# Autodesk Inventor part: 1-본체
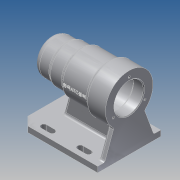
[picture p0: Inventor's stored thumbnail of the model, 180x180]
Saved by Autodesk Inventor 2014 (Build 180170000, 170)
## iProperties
Created: 2017-09
Part Number: 1-본체
Material: 알루미늄 6061
Document SubType Name: Modeling
Designer: kb542-15
Density: 2.71 g/cm^3
Appearance: 알루미늄 - 평지
Mass: 696.893 g
Surface Area: 708.801 cm^2
Volume: 257.156 cm^3
Author: kb542-15
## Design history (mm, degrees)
sketch "스케치1"
  geometry: L1 (-56, 0)-(56, 0); L2 (-56, 0)-(-56, 25); L3 (-56, 25)-(-31, 25); L4 (-31, 25)-(-31, 27); L5 (-31, 27)-(-11, 27); L6 (-11, 27)-(-11, 30); L7 (-11, 30)-(28, 30); L8 (28, 30)-(28, 34); L9 (28, 34)-(56, 34); L10 (56, 34)-(56, 21); L11 (56, 21)-(41, 21); L12 (41, 21)-(41, 24); L13 (41, 24)-(-13, 24); L14 (-13, 24)-(-13, 21); L15 (-13, 21)-(-25, 21); L16 (-25, 21)-(-25, 17.5); L17 (-25, 17.5)-(-43, 17.5); L18 (-43, 17.5)-(-43, 16); L19 (-43, 16)-(-47, 16); L20 (-47, 16)-(-47, 10.5); L21 (-47, 10.5)-(-50, 10.5); L22 (-50, 10.5)-(-50, 0); 2 further points
  constraints: 44 end point, 13 parallel, 7 perpendicular, 1 coincident, 1 collinear, 1 horizontal, 1 midpoint, 1 point on line, 1 vertical alignment
  dimensions: "d0" = 112 distance of L1.start L1.end; "d1" = 25 distance of L2.end L3.end; "d2" = 45 distance from line of L2 L6.end; "d3" = 84 distance from line of L8.end L2; "d4" = 21 diameter of L21 L1; "d5" = 32 diameter of L19 L1; "d6" = 35 diameter of L17 L1; "d7" = 42 diameter of L15 L1; "d8" = 48 diameter of L13 L1; "d9" = 42 diameter of L11 L1; "d10" = 50 diameter of L3 L1; "d11" = 54 diameter of L5 L1; "d12" = 60 diameter of L7 L1; "d13" = 68 diameter of L9 L1; "d14" = 15 distance of L10.end L11.end; "d15" = 54 distance of L12.end L13.end; "d16" = 12 distance of L14.end L15.end; "d17" = 18 distance of L16.end L17.end; "d18" = 4 distance of L18.end L19.end; "d19" = 3 distance of L20.end L21.end
revolve "회전1" sketch "스케치1" stored, may be unused: angle "d20" = 90 deg
node "작업 평면1"
sketch "스케치2"
  geometry: L1 (-56, -45)-(56, -45); L2 (56, -45)-(56, 45); L3 (56, 45)-(-56, 45); L4 (-56, 45)-(-56, -45); L5 (-56, -45)-(56, 45); L6 (56, -45)-(-56, 45); 1 further point
  constraints: 12 end point, 2 midpoint, 2 parallel, 1 horizontal, 1 perpendicular
  dimensions: "d22" = 112 distance of L2.end L3.end; "d23" = 90 distance of L1.end L2.end
extrude "돌출1" join sketch "스케치2" distance "d24" = 8; taper "d25" = 0 deg
sketch "스케치3"
  geometry: L1 (70, -45)-(70, 45) reference; L2 (70, 45)-(62, 45) reference; L3 (62, -45)-(62, 45) reference; L4 (70, -45)-(62, -45) reference; L5 (62, -35)-(26.008, -21.9); L6 (62, 35)-(26.008, 21.9); A1 r 34 centre (0, 0) between (26.008, -21.9) and (26.008, 21.9) reference
  constraints: 4 end point, 2 point on circle, 2 point on line
  dimensions: "d26" = 110 deg angle of L3 L5; "d27" = 110 deg angle of L3 L6; "d28" = 10 distance from line of L5.start L4; "d29" = 10 distance of L2.end L6.start
extrude "돌출2" join sketch "스케치3" distance "d30" = 8; taper "d31" = 0 deg
sketch "스케치4"
  geometry: L1 (56, 25)-(56, -25) reference; L2 (56, -25)-(31, -25) reference; L3 (31, -25)-(31, -27) reference; L4 (31, -27)-(11, -27) reference; L5 (11, -27)-(11, -30) reference; L6 (11, -30)-(-28, -30) reference; L7 (-28, -30)-(-28, -34) reference; L8 (-28, -34)-(-48, -34) reference; L9 (-48, -34)-(-48, -62) reference; L10 (-48, -62)-(56, -62) reference; L11 (56, -62)-(56, -70) reference; L12 (56, -70)-(-56, -70) reference; L13 (-56, -70)-(-56, -21) reference; L14 (-56, -21)-(-41, -21) reference; L15 (-41, -21)-(-41, -24) reference; L16 (-41, -24)-(13, -24) reference; L17 (13, -24)-(13, -21) reference; L18 (13, -21)-(25, -21) reference; L19 (25, -21)-(25, -17.5) reference; L20 (25, -17.5)-(43, -17.5) reference; L21 (43, -17.5)-(43, -16) reference; L22 (43, -16)-(47, -16) reference; L23 (47, -16)-(47, -10.5) reference; L24 (47, -10.5)-(50, -10.5) reference; L25 (50, -10.5)-(50, 10.5) reference; L26 (50, 10.5)-(47, 10.5) reference; L27 (47, 10.5)-(47, 16) reference; L28 (47, 16)-(43, 16) reference; L29 (43, 16)-(43, 17.5) reference; L30 (43, 17.5)-(25, 17.5) reference; L31 (25, 17.5)-(25, 21) reference; L32 (25, 21)-(13, 21) reference; L33 (13, 21)-(13, 24) reference; L34 (13, 24)-(-41, 24) reference; L35 (-41, 24)-(-41, 21) reference; L36 (-41, 21)-(-56, 21) reference; L37 (-56, 21)-(-56, 34) reference; L38 (-56, 34)-(-28, 34) reference; L39 (-28, 34)-(-28, 30) reference; L40 (-28, 30)-(11, 30) reference; L41 (11, 30)-(11, 27) reference; L42 (11, 27)-(31, 27) reference; L43 (31, 27)-(31, 25) reference; L44 (31, 25)-(56, 25) reference; L45 (34, -62)-(24.622, -27); 1 further point
  constraints: 2 end point, 2 point on line
  dimensions: "d32" = 22 distance from line of L45.start L11; "d33" = 105 deg angle of L45 L10
feature "리브1" sketch "스케치4" dims "d34" = 1, "d35" = 8, "d36" = 0, "d37" = 0, "d38" = 1, "d39" = 1
sketch "스케치5"
  geometry: L1 (48, -4)-(-34, -4) reference; L2 (56, -45)-(56, -35) reference; L3 (32, -34)-(20, -34); L4 (32, -30)-(20, -30); L5 (20, -38)-(32, -38); L6 (-20, -34)-(-32, -34); L7 (-20, -30)-(-32, -30); L8 (-32, -38)-(-20, -38); A1 r 4 centre (32, -34) between (32, -38) and (32, -30); A2 r 4 centre (20, -34) between (20, -30) and (20, -38); A3 r 4 centre (-20, -34) between (-20, -38) and (-20, -30); A4 r 4 centre (-32, -34) between (-32, -30) and (-32, -38); 3 further points
  constraints: 16 end point, 8 point on circle, 8 tangent, 4 centre point, 4 parallel, 2 midpoint, 1 horizontal alignment
  dimensions: "d40" = 24 distance from line of L2 L3.start; "d41" = 12 distance of L3.start L3.end; "d42" = 4 radius of A1; "d43" = 34 vertical distance of point (0, 0) L3.start; "d44" = 4 radius of A4; "d45" = 12 distance of L6.start L6.end; "d46" = 40 distance of L3.end L6.start
extrude "돌출3" cut sketch "스케치5" stored distance "d47" = 8; taper "d48" = 0 deg
chamfer "모따기1" distance "d49" = 12; stored, may be unused: second distance "d50" = 2, angle "d51" = 45 deg
sketch "스케치6"
  geometry: C1 r 21 at (-70, 45) reference; 1 further point
  constraints: 1 horizontal alignment
  dimensions: "d52" = 26 distance of point (-96, 45) C1.centre
hole "구멍1" sketch "스케치6" at (-96, 45) diameter "d53" = 3.242; stored, may be unused: countersink angle "d57" = 90 deg, drill point angle "d59" = 118 deg; dims "d54" = 8, "d55" = 4, "d56" = 2, "d58" = 11
fillet "모깎기1" dims "d63" = 3
fillet "모깎기7" dims "d75" = 3
fillet "모깎기2" dims "d64" = 3
fillet "모깎기3" dims "d65" = 3
fillet "모깎기4" dims "d66" = 3
fillet "모깎기5" dims "d67" = 9
chamfer "모따기2" distance "d68" = 1; stored, may be unused: second distance "d69" = 2, angle "d70" = 45 deg
node "작업 평면2"
sketch "스케치7"
  geometry: L1 (47.5, -24.711)-(47.5, 34) reference; 2 further points
  constraints: 1 horizontal alignment, 1 other
  dimensions: "d71" = 48 distance from line of L1 point (-0.5, 0)
feature "엠보싱1" sketch "스케치7" dims "d14" = 15, "d72" = 0.5, "d73" = 0
fillet "모깎기6" dims "d74" = 0.3
node "솔리드1"
mirror "대칭1"
pattern_circular "원형 패턴1" dims angle "d61" = 360 deg
node "투영된 루프1"
node "절단 모서리 투영1"
